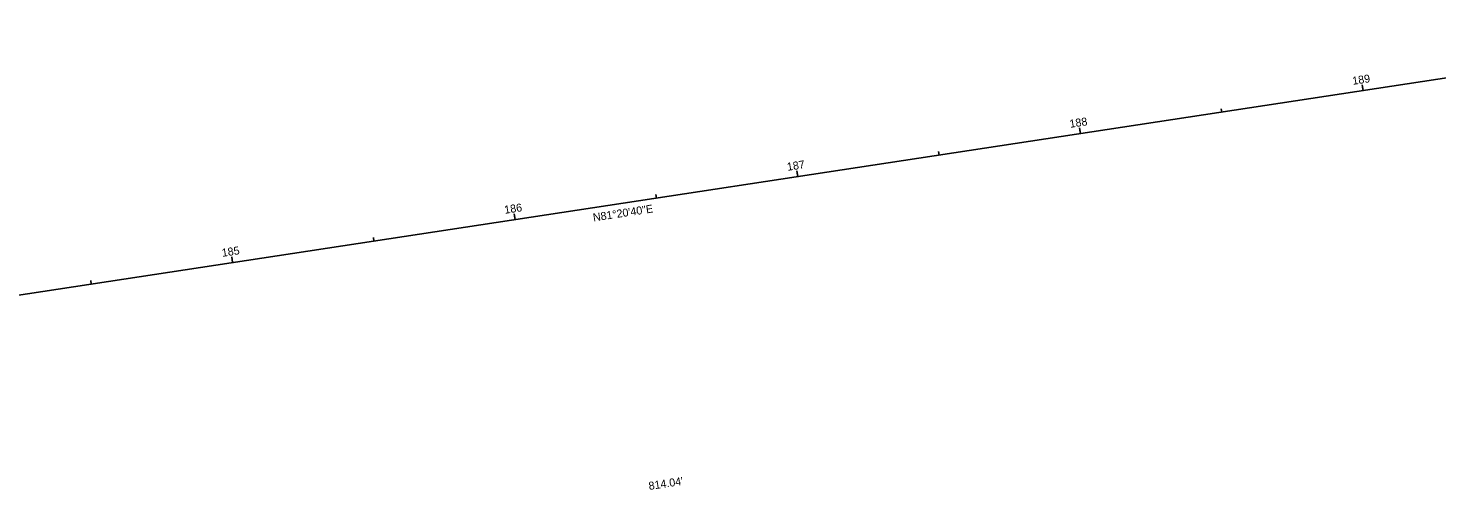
# Model space of a CAD drawing. Extents: x 1501024 to 1508874, y 327839 to 328839.
# Drawn here: x 1506408.9 to 1506901.6, y 328036.2 to 328197.9 of the extents above; entities that cross this region are included whole.
import ezdxf

# ---------------------------------------------------------------- set-up
doc = ezdxf.new("R2010")
doc.units = 0
for name, color, linetype in [('GE_X_Alignment', 7, 'Continuous'), ('GE_X_Alignment_100_Bearings', 7, 'Continuous'), ('GE_X_Alignment_100_Distances', 7, 'Continuous'), ('GE_X_Alignment_100_Stations', 7, 'Continuous'), ('GE_X_Alignment_500_Bearings', 7, 'Continuous'), ('GE_X_Alignment_500_Distances', 7, 'Continuous'), ('GE_X_Alignment_500_Stations', 7, 'Continuous')]:
    doc.layers.add(name, color=color, linetype=linetype)

msp = doc.modelspace()

# ---------------------------------------------------------------- linework, layer by layer
at = {"layer": 'GE_X_Alignment'}
msp.add_line((1506214.56, 328075.36), (1507019.33, 328197.87), dxfattribs=at)
at = {"layer": 'GE_X_Alignment_100_Stations'}
for p, q in [((1506875.84, 328176.02), (1506875.54, 328178)), ((1506826.41, 328168.5), (1506826.23, 328169.68)), ((1506776.98, 328160.97), (1506776.68, 328162.95)), ((1506727.55, 328153.45), (1506727.37, 328154.63)), ((1506678.12, 328145.92), (1506677.82, 328147.9)), ((1506628.69, 328138.4), (1506628.51, 328139.58)), ((1506579.26, 328130.87), (1506578.96, 328132.85)), ((1506529.83, 328123.35), (1506529.65, 328124.54)), ((1506480.4, 328115.82), (1506480.1, 328117.8)), ((1506430.97, 328108.3), (1506430.79, 328109.49))]:
    msp.add_line(p, q, dxfattribs=at)
at = {"layer": 'GE_X_Alignment_500_Stations'}
for p, q in [((1506875.84, 328176.02), (1506875.66, 328177.21)), ((1506776.98, 328160.97), (1506776.8, 328162.16)), ((1506678.12, 328145.92), (1506677.94, 328147.11)), ((1506579.26, 328130.87), (1506579.08, 328132.06)), ((1506480.4, 328115.82), (1506480.1, 328117.8))]:
    msp.add_line(p, q, dxfattribs=at)

# ---------------------------------------------------------------- texts
at = {"layer": 'GE_X_Alignment_100_Bearings'}
msp.add_text('N81°20\'40"E', height=2.8, rotation=8.6556, dxfattribs=at).set_placement((1506606.68, 328130.19))
at = {"layer": 'GE_X_Alignment_100_Distances'}
msp.add_text("814.04'", height=2.8, rotation=8.6556, dxfattribs=at).set_placement((1506626.16, 328036.19))
at = {"layer": 'GE_X_Alignment_100_Stations'}
for s, p in [('189', (1506872.28, 328178.01)), ('188', (1506773.39, 328162.96)), ('187', (1506674.54, 328147.91)), ('186', (1506575.67, 328132.86)), ('185', (1506476.85, 328117.81))]:
    msp.add_text(s, height=2.8, rotation=8.6556, dxfattribs=at).set_placement(p)
at = {"layer": 'GE_X_Alignment_500_Bearings'}
msp.add_text('N81°20\'40"E', height=2.8, rotation=8.6556, dxfattribs=at).set_placement((1506606.68, 328130.19))
at = {"layer": 'GE_X_Alignment_500_Distances'}
msp.add_text("814.04'", height=2.8, rotation=8.6556, dxfattribs=at).set_placement((1506626.16, 328036.19))
at = {"layer": 'GE_X_Alignment_500_Stations'}
msp.add_text('185', height=2.8, rotation=8.6556, dxfattribs=at).set_placement((1506476.85, 328117.81))

doc.saveas('drawing.dxf')
